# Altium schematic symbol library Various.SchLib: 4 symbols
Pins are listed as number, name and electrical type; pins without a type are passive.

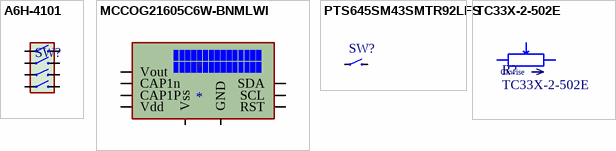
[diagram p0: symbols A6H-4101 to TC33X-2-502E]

## A6H-4101
designator SW?  (value not drawn)
DIP / SIP Switch, 4 Circuits, Slide, Surface Mount, SPST, 24 VDC, 25 mA; Manufacturer: Omron; Mfr Part Num.: A6H-4101; Voltage: 24V; Current: 25mA
footprint A6H-4101
pins: 1 Pin 1, 2 Pin 2, 3 Pin 3, 4 Pin 4, 5 Pin 5, 6 Pin 6, 7 Pin 7, 8 Pin 8

## MCCOG21605C6W-BNMLWI
designator *
Alphanumeric LCD, 16 x 2, White on Blue, 3V to 5V, I2C, English, Japanese, Transmissive; Manufacturer: MIDAS; Mfr Part Num.: MCCOG21605C6W-BNMLWI
footprint MCCOG21605C6W-BNMLWI
pins: 1 Vout (power), 2 CAP1n (power), 3 CAP1P (power), 4 Vdd (power), 5 Vss (power), 6 SDA (io), 7 SCL (io), 8 RST (in), G1 GND (power), G2 GND (power)

## PTS645SM43SMTR92LFS
designator SW?  (value not drawn)
Tactile Switch, PT645, Top Actuated, Surface Mount, Round Button, 160 gf, 50mA at 12VDC; Manufacturer: C&K Components; Mfr Part Num.: PTS645SM43SMTR92LFS; Voltage: 12V
footprint Pushbutton_6x6mm (Tactile Switch)
pins: 1 Pin 1, 2 Pin 2, 3 Pin 3, 4 Pin 4

## TC33X-2-502E
designator R?
Trimpot, Single Turn, Cermet, Top Adjust, 5 kohm, Surface Mount, 1 Turns; Manufacturer: Bourns; Power Rating: 100mW; Value: 5k
footprint TC33X-2
pins: 1 Pin 1 (power), 2 Pin 2 (power), 3 Pin 3 (power)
